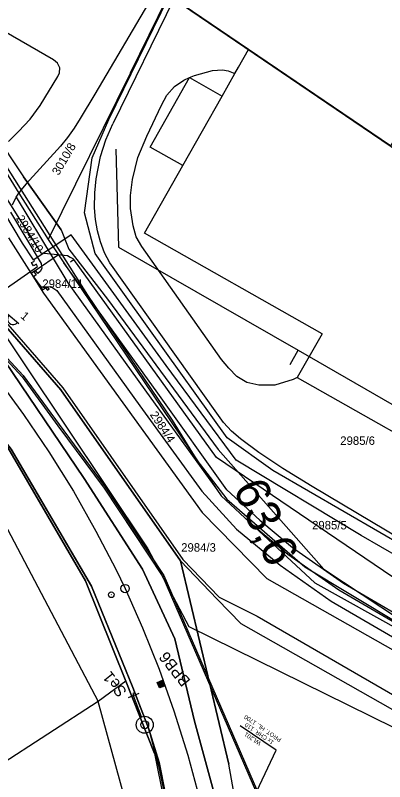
# Model space of a CAD drawing. Extents: x -620624 to -619936, y -1122925 to -1122325.
# Drawn here: x -620172.4 to -620107.1, y -1122855.2 to -1122719.7 of the extents above; entities that cross this region are included whole.
import ezdxf

# ---------------------------------------------------------------- set-up
doc = ezdxf.new("R2010")
doc.units = 0
for name, color, linetype in [('060603_ROZVODY_NN', 7, 'Continuous'), ('CETIN', 7, 'Continuous'), ('GasNet', 7, 'Continuous'), ('POPIS KABELOVÉ TRASY', 7, 'Continuous'), ('PS 06-14-01_trasa_sdělovací_nové', 7, 'Continuous'), ('RÁMY', 7, 'Continuous'), ('SSZT', 7, 'Continuous'), ('SSZT-DK', 7, 'Continuous'), ('SSZT-TK', 7, 'Continuous'), ('STÁVAJÍCÍ STOŽÁRY ODHAD', 7, 'Continuous'), ('VAS stoka', 7, 'Continuous'), ('VAS vodovod', 7, 'Continuous'), ('Vrstva 1', 7, 'Continuous'), ('Vrstva 2', 7, 'Continuous'), ('Vrstva 3', 7, 'Continuous'), ('Vrstva 53', 7, 'Continuous'), ('Vrstva 55', 7, 'Continuous'), ('Vrstva 56', 7, 'Continuous'), ('Vrstva 57', 7, 'Continuous'), ('Vrstva 7', 7, 'Continuous'), ('ČD-T', 7, 'Continuous')]:
    doc.layers.add(name, color=color, linetype=linetype)

msp = doc.modelspace()

# ---------------------------------------------------------------- linework, layer by layer
at = {"layer": '060603_ROZVODY_NN'}
msp.add_lwpolyline([(-620240.17, -1122718.34), (-620228.34, -1122728.07), (-620221.17, -1122735.76), (-620213.63, -1122742.04), (-620205.95, -1122748.19), (-620177.51, -1122774.52), (-620185.52, -1122781.05), (-620181.59, -1122785.57), (-620173.13, -1122796.4), (-620158.91, -1122820.61), (-620151.64, -1122838.53), (-620148.85, -1122845.74), (-620146.97, -1122851.79), (-620142.65, -1122873.56), (-620132.31, -1122871.72), (-620130.54, -1122883.68), (-620130.19, -1122888.41), (-620130.04, -1122888.39)], dxfattribs=at)
at = {"layer": 'CETIN'}
for points in [[(-620322.39, -1122622.26), (-620301.06, -1122636.75), (-620273.54, -1122652.22), (-620253.25, -1122663.16), (-620204.02, -1122698.84), (-620159.64, -1122769.19), (-620144.67, -1122791.29), (-620140.33, -1122798.33), (-620134.98, -1122805.25), (-620121.23, -1122817.18), (-620095.95, -1122832.42), (-620068, -1122848.18)], [(-620277.38, -1122640.15), (-620276.74, -1122645.99), (-620273.83, -1122650.1), (-620271.73, -1122651.88), (-620253.98, -1122661.12), (-620237.57, -1122672.68), (-620221.58, -1122684.68), (-620204.03, -1122697.14), (-620190.46, -1122716.45), (-620176.22, -1122740.39), (-620170.94, -1122748.28)], [(-620227.04, -1122727.67), (-620227.6, -1122728.26), (-620225.24, -1122730.07), (-620192.39, -1122755.87), (-620182.03, -1122766.47), (-620178.55, -1122770.03), (-620178.11, -1122770.48), (-620148.97, -1122814.05), (-620141.74, -1122827.78), (-620093.42, -1122851.53), (-620088.91, -1122854.99)], [(-620170.94, -1122748.28), (-620164.26, -1122757.63)], [(-620164.26, -1122757.63), (-620170.94, -1122748.28)], [(-620164.26, -1122757.63), (-620162.95, -1122761.03), (-620156.11, -1122769.9), (-620136.56, -1122796.46), (-620117.89, -1122817.63), (-620104.34, -1122826.6), (-620099.09, -1122828.81), (-620092.09, -1122832.08), (-620086.33, -1122833.54), (-620081.02, -1122834.31)]]:
    msp.add_lwpolyline(points, dxfattribs=at)
at = {"layer": 'GasNet'}
for points in [[(-620169.19, -1122762.97), (-620171.1, -1122759.99), (-620177.21, -1122749.83), (-620183.11, -1122739.88), (-620187.41, -1122733.49), (-620188.17, -1122734.04)], [(-620049.65, -1122846.64), (-620053.62, -1122841.38), (-620061.16, -1122831.41), (-620068.48, -1122836.5), (-620088.2, -1122824.99), (-620093.66, -1122821.84), (-620093.89, -1122821.71), (-620111.26, -1122811.68), (-620133.38, -1122798.37), (-620145.72, -1122781.6), (-620162.54, -1122758.52), (-620166.3, -1122761.04), (-620166.89, -1122761.43), (-620167.47, -1122761.82), (-620169.13, -1122762.93), (-620169.19, -1122762.97)], [(-620169.25, -1122763.27), (-620169, -1122763.15), (-620169.13, -1122762.93)], [(-620203.57, -1122783.96), (-620188.33, -1122778.28), (-620177.56, -1122770.44), (-620168.45, -1122764.1), (-620168.62, -1122763.79), (-620168.66, -1122763.73), (-620169.16, -1122764.02), (-620169.5, -1122763.44), (-620169.25, -1122763.27)]]:
    msp.add_lwpolyline(points, dxfattribs=at)
at = {"layer": 'POPIS KABELOVÉ TRASY'}
msp.add_line((-620132.62, -1122845.33), (-620132.62, -1122845.33), dxfattribs=at)
msp.add_line((-620132.62, -1122845.33), (-620132.62, -1122845.33), dxfattribs=at)
msp.add_lwpolyline([(-620137.15, -1122872.57), (-620126.3, -1122849.62), (-620132.62, -1122845.33)], dxfattribs=at)
at = {"layer": 'PS 06-14-01_trasa_sdělovací_nové'}
msp.add_lwpolyline([(-620232.13, -1122718.84), (-620235.04, -1122722.56), (-620243.03, -1122716), (-620248.32, -1122722.77), (-620228.5, -1122738.51), (-620211.63, -1122752.65), (-620198.93, -1122763.63), (-620190.05, -1122772.28), (-620190.33, -1122775.52), (-620181.59, -1122785.57), (-620173.13, -1122796.4), (-620158.91, -1122820.61), (-620151.64, -1122838.53), (-620148.85, -1122845.74), (-620147.08, -1122852.39), (-620142.65, -1122873.56), (-620132.31, -1122871.72), (-620130.54, -1122883.68), (-620129.88, -1122892.6), (-620129.3, -1122896.72), (-620128.98, -1122906.78)], dxfattribs=at)
at = {"layer": 'RÁMY'}
for points in [[(-620540.39, -1122447.87), (-620019.21, -1122801.81), (-620102.64, -1122924.66), (-620623.82, -1122570.71)], [(-620109.51, -1122560.98), (-620022.64, -1122619.97), (-620106.07, -1122742.82), (-620192.94, -1122683.83)], [(-620366.66, -1122565.85), (-620019.21, -1122801.81), (-620102.64, -1122924.66), (-620450.09, -1122688.7)]]:
    msp.add_lwpolyline(points, close=True, dxfattribs=at)
at = {"layer": 'SSZT'}
msp.add_lwpolyline([(-620131.71, -1122887.84), (-620132.1, -1122876.02), (-620140.7, -1122844.51), (-620144.18, -1122829.91), (-620149.89, -1122817.62), (-620160.22, -1122801.59), (-620175.65, -1122778.86), (-620179.82, -1122771.9), (-620189.29, -1122760.71), (-620207.42, -1122744.25), (-620237.07, -1122720.47), (-620255.6, -1122705.52), (-620251.36, -1122700.2)], dxfattribs=at)
at = {"layer": 'SSZT-DK'}
msp.add_lwpolyline([(-620414.39, -1122636.12), (-620392.31, -1122655.21), (-620359.04, -1122685.8), (-620308.77, -1122717.8), (-620291.41, -1122732.21), (-620277.2, -1122744.11), (-620257.61, -1122720.05), (-620250.25, -1122710.72), (-620233.29, -1122724.26), (-620218.7, -1122737.68), (-620210.44, -1122746.52), (-620193.32, -1122761.99), (-620178.35, -1122775.89), (-620171.18, -1122783.62), (-620164.84, -1122792.28), (-620156.69, -1122803.31), (-620146.31, -1122818.99), (-620117.64, -1122885.13), (-620110.3, -1122902.14)], dxfattribs=at)
at = {"layer": 'SSZT-TK'}
msp.add_lwpolyline([(-620251.55, -1122700.3), (-620255.6, -1122705.52), (-620237.07, -1122720.47), (-620207.42, -1122744.25), (-620189.29, -1122760.71), (-620179.82, -1122771.9), (-620175.65, -1122778.86), (-620160.22, -1122801.59), (-620149.89, -1122817.62), (-620144.18, -1122829.91), (-620140.7, -1122844.51), (-620132.1, -1122876.02), (-620131.71, -1122886.93), (-620131.71, -1122887.84), (-620128.5, -1122887.82), (-620131.71, -1122887.84), (-620131.71, -1122904.92)], dxfattribs=at)
at = {"layer": 'STÁVAJÍCÍ STOŽÁRY ODHAD'}
msp.add_line((-620173.73, -1122772.54), (-620171.75, -1122774.22), dxfattribs=at)
msp.add_arc((-620172.75, -1122773.39), 1, 139.0457, 320.4509, dxfattribs=at)
at = {"layer": 'VAS stoka'}
for p, q in [((-620154.6, -1122743.36), (-620154.17, -1122760.72)), ((-620154.17, -1122760.72), (-620122.37, -1122778.92)), ((-620123.82, -1122781.44), (-620122.37, -1122778.92)), ((-620122.37, -1122778.92), (-620079.03, -1122803.96))]:
    msp.add_line(p, q, dxfattribs=at)
at = {"layer": 'VAS vodovod'}
for points in [[(-620187.76, -1122731.9), (-620187.61, -1122732.17), (-620187.46, -1122732.43), (-620186.51, -1122732.96), (-620185.56, -1122733.49), (-620182.4, -1122738.6), (-620179.23, -1122743.71), (-620175.45, -1122749.73), (-620171.67, -1122755.74), (-620169.77, -1122758.72), (-620167.87, -1122761.69), (-620165.51, -1122761.94), (-620163.14, -1122762.19), (-620162.67, -1122762.45), (-620162.19, -1122762.71)], [(-620162.62, -1122763.32), (-620162.32, -1122763.04), (-620162.06, -1122762.89)], [(-620094.32, -1122826.78), (-620136.84, -1122797.89), (-620162.06, -1122762.89), (-620162.19, -1122762.71)]]:
    msp.add_lwpolyline(points, dxfattribs=at)
at = {"layer": 'Vrstva 1'}
for points in [[(-620176.09, -1122783.33), (-620170.93, -1122790.27), (-620166.46, -1122796.85), (-620162.11, -1122803.84), (-620158.13, -1122810.88), (-620154.63, -1122817.64), (-620152.99, -1122821.05), (-620149.89, -1122827.96), (-620146.96, -1122835.3), (-620144.34, -1122842.64), (-620141.9, -1122850.48), (-620139.85, -1122858.17), (-620138.09, -1122866.06), (-620136.62, -1122873.96), (-620135.51, -1122881.84), (-620134.9, -1122887.57), (-620134.42, -1122893.91), (-620134.34, -1122895.32), (-620134.21, -1122898.3), (-620134.18, -1122899.02), (-620134.11, -1122903.29)], [(-620151.28, -1122839.45), (-620151.64, -1122838.53), (-620158.91, -1122820.61), (-620164.59, -1122810.94), (-620173.13, -1122796.4), (-620173.84, -1122795.49)], [(-620151.28, -1122839.45), (-620151.63, -1122839.59), (-620151.49, -1122839.98)], [(-620140.39, -1122873.11), (-620142.65, -1122873.56), (-620146.97, -1122851.79), (-620148.85, -1122845.74), (-620151.28, -1122839.45)]]:
    msp.add_lwpolyline(points, dxfattribs=at)
at = {"layer": 'Vrstva 2'}
for p, q in [((-620147.28, -1122837.75), (-620146.07, -1122838.27)), ((-620147.26, -1122837.61), (-620145.98, -1122838.16)), ((-620147.09, -1122837.54), (-620146.05, -1122837.99)), ((-620146.92, -1122837.47), (-620146.12, -1122837.82)), ((-620146.75, -1122837.4), (-620146.19, -1122837.64)), ((-620146.58, -1122837.33), (-620146.26, -1122837.47)), ((-620146.4, -1122837.27), (-620146.33, -1122837.3)), ((-620147.21, -1122837.92), (-620146.25, -1122838.33)), ((-620147.14, -1122838.09), (-620146.42, -1122838.4)), ((-620147.07, -1122838.26), (-620146.59, -1122838.47)), ((-620147, -1122838.44), (-620146.76, -1122838.54)), ((-620150.55, -1122839.62), (-620152.42, -1122840.34)), ((-620150.06, -1122843.72), (-620151.49, -1122839.98))]:
    msp.add_line(p, q, dxfattribs=at)
msp.add_lwpolyline([(-620146.35, -1122837.24), (-620145.96, -1122838.22), (-620146.93, -1122838.61), (-620147.32, -1122837.63)], close=True, dxfattribs=at)
msp.add_lwpolyline([(-620146.35, -1122837.24), (-620145.96, -1122838.22), (-620146.93, -1122838.61), (-620147.32, -1122837.63)], close=True, dxfattribs=at)
for radius in [1.5, 0.7]:
    msp.add_circle((-620149.52, -1122845.12), radius, dxfattribs=at)
at = {"layer": 'Vrstva 53'}
for p, q in [((-620174.83, -1122773.82), (-620164.34, -1122785.91)), ((-620164.34, -1122785.91), (-620143.18, -1122816.17)), ((-620159.98, -1122819.68), (-620173.68, -1122796.12)), ((-620143.18, -1122816.17), (-620134.66, -1122852.11)), ((-620152.84, -1122837.4), (-620159.98, -1122819.68)), ((-620147.76, -1122850.22), (-620152.84, -1122837.4))]:
    msp.add_line(p, q, dxfattribs=at)
at = {"layer": 'Vrstva 55'}
for p, q in [((-620148.19, -1122716.42), (-620158.35, -1122733.67)), ((-620155.87, -1122738.11), (-620145.18, -1122716.27)), ((-620152.03, -1122729.88), (-620145.31, -1122716.18)), ((-620165.63, -1122727.6), (-620176.88, -1122721.09)), ((-620132.92, -1122728.86), (-620131.17, -1122725.78)), ((-620164.91, -1122728.17), (-620165.63, -1122727.6)), ((-620164.53, -1122728.99), (-620164.91, -1122728.17)), ((-620164.6, -1122729.87), (-620164.53, -1122728.99)), ((-620133.58, -1122730.02), (-620132.92, -1122728.86)), ((-620167.98, -1122735.66), (-620164.86, -1122730.54)), ((-620152.03, -1122729.88), (-620166.6, -1122759.34)), ((-620164.86, -1122730.54), (-620164.6, -1122729.87)), ((-620148.58, -1122743.04), (-620141.6, -1122730.74)), ((-620141.6, -1122730.74), (-620135.85, -1122734.02)), ((-620135.85, -1122734.02), (-620133.58, -1122730.02)), ((-620158.35, -1122733.67), (-620160.91, -1122737.97)), ((-620169.77, -1122738.05), (-620167.98, -1122735.66)), ((-620171.8, -1122740.25), (-620169.77, -1122738.05)), ((-620160.91, -1122737.97), (-620161.97, -1122739.66)), ((-620158.82, -1122744.94), (-620155.87, -1122738.11)), ((-620161.97, -1122739.66), (-620163.14, -1122741.3)), ((-620173.6, -1122742), (-620171.8, -1122740.25)), ((-620163.14, -1122741.3), (-620164.41, -1122742.85)), ((-620164.41, -1122742.85), (-620170.46, -1122749.51)), ((-620176.62, -1122743.36), (-620171.74, -1122751.13)), ((-620142.8, -1122746.27), (-620148.58, -1122743.04)), ((-620160.13, -1122754.62), (-620158.82, -1122744.94)), ((-620149.58, -1122758.23), (-620142.8, -1122746.27)), ((-620170.46, -1122749.51), (-620171.42, -1122750.65)), ((-620171.42, -1122750.65), (-620171.74, -1122751.13)), ((-620172.87, -1122753.23), (-620172.25, -1122751.89)), ((-620172.25, -1122751.89), (-620171.74, -1122751.13)), ((-620171.74, -1122751.13), (-620166.6, -1122759.34)), ((-620173.24, -1122754.52), (-620167.81, -1122763.6)), ((-620158.3, -1122761.8), (-620160.13, -1122754.62)), ((-620118.17, -1122776.02), (-620149.58, -1122758.23)), ((-620166.6, -1122759.34), (-620164.75, -1122762.08)), ((-620148.77, -1122775.1), (-620158.3, -1122761.8)), ((-620165.7, -1122762.73), (-620167.73, -1122764.1)), ((-620164.75, -1122762.08), (-620165.7, -1122762.73)), ((-620164.75, -1122762.08), (-620163.81, -1122763.48)), ((-620167.73, -1122764.1), (-620169.61, -1122765.37)), ((-620167.81, -1122763.6), (-620167.73, -1122764.1)), ((-620163.81, -1122763.48), (-620136.79, -1122803.52)), ((-620147.22, -1122786.5), (-620163.81, -1122763.48)), ((-620169.61, -1122765.37), (-620169.18, -1122765.95)), ((-620169.18, -1122765.95), (-620167.55, -1122768.23)), ((-620169.18, -1122765.95), (-620167.86, -1122767.72)), ((-620167.86, -1122767.72), (-620166.7, -1122767.69)), ((-620167.55, -1122768.23), (-620167.06, -1122767.87)), ((-620167.06, -1122767.87), (-620166.72, -1122768.33)), ((-620166.72, -1122768.33), (-620166.41, -1122768.09)), ((-620166.7, -1122767.69), (-620166.09, -1122767.67)), ((-620166.41, -1122768.09), (-620166.7, -1122767.69)), ((-620166.09, -1122767.67), (-620165.02, -1122768.39)), ((-620165.02, -1122768.39), (-620150.35, -1122788.75)), ((-620164.34, -1122785.91), (-620174.83, -1122773.82)), ((-620134.93, -1122794.41), (-620148.77, -1122775.1)), ((-620118.17, -1122776.02), (-620122.58, -1122783.75)), ((-620143.18, -1122816.17), (-620164.34, -1122785.91)), ((-620134.98, -1122803.58), (-620147.22, -1122786.5)), ((-620150.35, -1122788.75), (-620139.43, -1122803.84)), ((-620126.88, -1122800.18), (-620134.93, -1122794.41)), ((-620173.68, -1122796.12), (-620159.98, -1122819.68)), ((-620107.97, -1122811.15), (-620126.88, -1122800.18)), ((-620139.43, -1122803.84), (-620133.3, -1122810.53)), ((-620136.79, -1122803.52), (-620136, -1122804.68)), ((-620129.15, -1122808.98), (-620134.98, -1122803.58)), ((-620136, -1122804.68), (-620130.17, -1122810.08)), ((-620129.15, -1122808.98), (-620123.37, -1122813.77)), ((-620133.3, -1122810.53), (-620125.58, -1122816.92)), ((-620130.17, -1122810.08), (-620119.48, -1122820.03)), ((-620079.47, -1122827.69), (-620107.97, -1122811.15)), ((-620123.37, -1122813.77), (-620114.36, -1122820.1)), ((-620136.72, -1122822.9), (-620143.18, -1122816.17)), ((-620134.66, -1122852.11), (-620143.18, -1122816.17)), ((-620125.58, -1122816.92), (-620116.57, -1122823.25)), ((-620159.98, -1122819.68), (-620152.84, -1122837.4)), ((-620119.48, -1122820.03), (-620072.47, -1122846.25)), ((-620114.36, -1122820.1), (-620093.24, -1122832.45)), ((-620132.47, -1122827.27), (-620136.72, -1122822.9)), ((-620116.57, -1122823.25), (-620095.17, -1122835.78)), ((-620080.86, -1122856.55), (-620132.47, -1122827.27)), ((-620152.84, -1122837.4), (-620157.72, -1122840.99)), ((-620152.84, -1122837.4), (-620147.76, -1122850.22)), ((-620157.72, -1122840.99), (-620192.57, -1122863.59)), ((-620147.76, -1122850.22), (-620140.56, -1122886.8)), ((-620129.18, -1122882.66), (-620134.66, -1122852.11))]:
    msp.add_line(p, q, dxfattribs=at)
msp.add_lwpolyline([(-620122.58, -1122783.75), (-620090.7, -1122801.75), (-620090.59, -1122801.55)], dxfattribs=at)
at = {"layer": 'Vrstva 56'}
for p, q in [((-620144.36, -1122716.82), (-620155.13, -1122738.93)), ((-620137.55, -1122729.49), (-620135.75, -1122729.37)), ((-620135.75, -1122729.37), (-620134.75, -1122729.52)), ((-620142.59, -1122731.16), (-620141.6, -1122730.74)), ((-620141.6, -1122730.74), (-620140.72, -1122730.36)), ((-620140.72, -1122730.36), (-620137.55, -1122729.49)), ((-620134.75, -1122729.52), (-620133.58, -1122730.02)), ((-620144.26, -1122732.31), (-620142.59, -1122731.16)), ((-620145.58, -1122733.83), (-620144.26, -1122732.31)), ((-620146.56, -1122735.6), (-620145.58, -1122733.83)), ((-620142.8, -1122746.27), (-620135.85, -1122734.02)), ((-620149.15, -1122741.1), (-620146.56, -1122735.6)), ((-620156.36, -1122741.72), (-620155.13, -1122738.93)), ((-620150.71, -1122744.84), (-620149.15, -1122741.1)), ((-620157.32, -1122744.66), (-620156.36, -1122741.72)), ((-620158.07, -1122748.62), (-620157.32, -1122744.66)), ((-620151.67, -1122748.77), (-620150.71, -1122744.84)), ((-620158.33, -1122751.09), (-620158.07, -1122748.62)), ((-620152.03, -1122751.56), (-620151.67, -1122748.77)), ((-620172.25, -1122751.89), (-620165.7, -1122762.73)), ((-620158.37, -1122753.78), (-620158.33, -1122751.09)), ((-620152.03, -1122753.86), (-620152.03, -1122751.56)), ((-620158.2, -1122755.8), (-620158.37, -1122753.78)), ((-620151.58, -1122756.91), (-620152.03, -1122753.86)), ((-620157.86, -1122757.82), (-620158.2, -1122755.8)), ((-620157.34, -1122759.76), (-620157.86, -1122757.82)), ((-620151.04, -1122758.86), (-620151.58, -1122756.91)), ((-620173.61, -1122759.06), (-620169.61, -1122765.37)), ((-620150.03, -1122760.6), (-620151.04, -1122758.86)), ((-620156.64, -1122761.69), (-620157.34, -1122759.76)), ((-620155.67, -1122763.48), (-620156.64, -1122761.69)), ((-620135.93, -1122780.56), (-620150.03, -1122760.6)), ((-620165.7, -1122762.73), (-620163.11, -1122767.02)), ((-620167.68, -1122764.39), (-620167.95, -1122764.93)), ((-620167.73, -1122764.1), (-620167.68, -1122764.39)), ((-620136.78, -1122790.07), (-620155.67, -1122763.48)), ((-620169.61, -1122765.37), (-620167.41, -1122768.84)), ((-620168.7, -1122765.62), (-620169.18, -1122765.95)), ((-620168.75, -1122764.87), (-620169.05, -1122765.1)), ((-620169.05, -1122765.1), (-620168.7, -1122765.62)), ((-620168.38, -1122765.37), (-620168.75, -1122764.87)), ((-620167.95, -1122764.93), (-620168.38, -1122765.37)), ((-620163.11, -1122767.02), (-620148.44, -1122787.38)), ((-620167.41, -1122768.84), (-620139.39, -1122807.63)), ((-620174.45, -1122773.49), (-620163.96, -1122785.58)), ((-620134.64, -1122782.1), (-620135.93, -1122780.56)), ((-620133.21, -1122783.55), (-620134.64, -1122782.1)), ((-620131.49, -1122784.61), (-620133.21, -1122783.55)), ((-620163.96, -1122785.58), (-620142.77, -1122815.89)), ((-620148.44, -1122787.38), (-620136.79, -1122803.52)), ((-620185.65, -1122788.07), (-620157.72, -1122840.99)), ((-620135.58, -1122791.72), (-620136.78, -1122790.07)), ((-620134.2, -1122793.25), (-620135.58, -1122791.72)), ((-620132.61, -1122794.57), (-620134.2, -1122793.25)), ((-620129.33, -1122796.98), (-620132.61, -1122794.57)), ((-620125.13, -1122799.85), (-620129.33, -1122796.98)), ((-620119.93, -1122803.03), (-620125.13, -1122799.85)), ((-620104.17, -1122812.35), (-620119.93, -1122803.03)), ((-620139.39, -1122807.63), (-620127.92, -1122819.29)), ((-620124.23, -1122815), (-620130.17, -1122810.08)), ((-620142.77, -1122815.89), (-620136.36, -1122822.55)), ((-620115.22, -1122821.33), (-620124.23, -1122815)), ((-620127.92, -1122819.29), (-620075.39, -1122849.03)), ((-620093.98, -1122833.75), (-620115.22, -1122821.33)), ((-620136.36, -1122822.55), (-620129.64, -1122825.94)), ((-620129.64, -1122825.94), (-620104.21, -1122840.64)), ((-620149.02, -1122872.99), (-620157.72, -1122840.99))]:
    msp.add_line(p, q, dxfattribs=at)
msp.add_lwpolyline([(-620122.58, -1122783.75), (-620123.27, -1122784.1), (-620126.53, -1122785.08), (-620129.37, -1122785.1), (-620131.49, -1122784.61)], dxfattribs=at)
at = {"layer": 'Vrstva 7'}
msp.add_line((-620155.44, -1122822.09), (-620155.4, -1122822.18), dxfattribs=at)
for centre, radius in [((-620152.99, -1122821.05), 0.75), ((-620155.42, -1122822.14), 0.5)]:
    msp.add_circle(centre, radius, dxfattribs=at)
at = {"layer": 'ČD-T'}
msp.add_lwpolyline([(-620414.22, -1122635.87), (-620392.12, -1122654.98), (-620358.85, -1122685.56), (-620308.58, -1122717.56), (-620291.22, -1122731.97), (-620279.98, -1122741.46), (-620260.48, -1122717.47), (-620252.94, -1122708.19), (-620233.1, -1122724.03), (-620218.51, -1122737.45), (-620206.64, -1122747.53), (-620193.13, -1122761.76), (-620178.16, -1122775.66), (-620171, -1122783.39), (-620164.66, -1122792.05), (-620156.51, -1122803.08), (-620146.12, -1122818.76), (-620117.45, -1122884.9), (-620110.11, -1122901.9)], dxfattribs=at)

# ---------------------------------------------------------------- texts
at = {"layer": 'POPIS KABELOVÉ TRASY'}
for s, p in [('PROT. HL. 1700', (-620125.29, -1122847.61)), ('1x CHR. 110', (-620126.62, -1122848.06)), ('WL201', (-620128.88, -1122848.22))]:
    msp.add_text(s, height=0.75, rotation=145.8181, dxfattribs=at).set_placement(p)
at = {"layer": 'STÁVAJÍCÍ STOŽÁRY ODHAD'}
msp.add_text('1', height=1.5, rotation=319.7483, dxfattribs=at).set_placement((-620171.57, -1122773.08))
at = {"layer": 'Vrstva 3'}
for s, p in [('BPB6', (-620141.32, -1122837.34)), ('Se1', (-620152.57, -1122839.22))]:
    msp.add_text(s, height=2, rotation=128.542, dxfattribs=at).set_placement(p)
at = {"layer": 'Vrstva 57'}
for s, rotation, p in [('3010/8', 59.4683, (-620164.72, -1122748.13)), ('2984/10', 300.8806, (-620172.31, -1122755.59)), ('2984/4', 303.3, (-620148.65, -1122790.32))]:
    msp.add_text(s, height=1.5, rotation=rotation, dxfattribs=at).set_placement(p)
for s, p in [('2984/11', (-620167.61, -1122767.91)), ('2985/6', (-620114.96, -1122795.65)), ('2985/5', (-620119.94, -1122810.59)), ('2984/3', (-620143.07, -1122814.53))]:
    msp.add_text(s, height=1.5, dxfattribs=at).set_placement(p)
at = {"layer": 'Vrstva 7'}
msp.add_text('63,6', height=6, rotation=294.1767, dxfattribs=at).set_placement((-620133.97, -1122803.32))

doc.saveas('drawing.dxf')
